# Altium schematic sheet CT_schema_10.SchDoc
size 274 x 160 mm
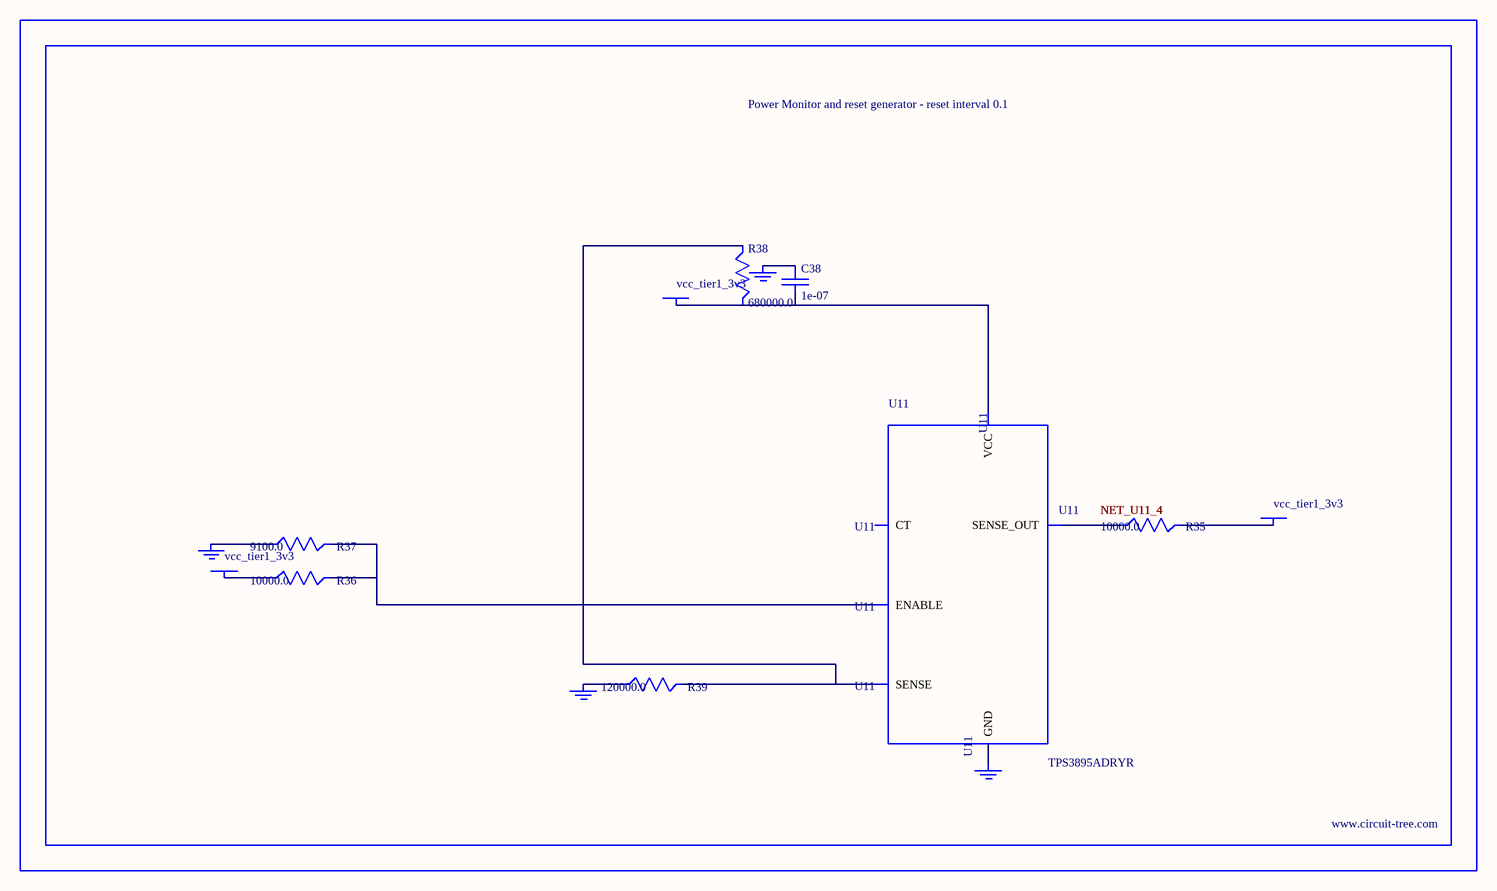
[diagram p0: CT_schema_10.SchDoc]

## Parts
BORDER9  (no value)
C38  1e-07  [C0402]
GND_INSTANCE_9_0  (no value)
GND_INSTANCE_9_1  (no value)
GND_INSTANCE_9_2  (no value)
GND_INSTANCE_9_3  (no value)
POWER_INSTANCE_9_0  vcc_tier1_3v3
POWER_INSTANCE_9_1  vcc_tier1_3v3
POWER_INSTANCE_9_2  vcc_tier1_3v3
R35  10000.0  [R0603]
R36  10000.0  [R0603]
R37  9100.0  [R0603]
R38  680000.0  [R0603]
R39  120000.0  [R0603]
U11  TPS3895ADRYR  [SON-6]

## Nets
NetC38_1: C38.1 GND_INSTANCE_9_2.0(GND)
NetC38_2: C38.2 POWER_INSTANCE_9_2.0(PWR) R38.2 U11.6(VCC)
NetGND_INSTANCE_9_0_0: GND_INSTANCE_9_0.0(GND) R37.1
NetGND_INSTANCE_9_1_0: GND_INSTANCE_9_1.0(GND) R39.1
NetGND_INSTANCE_9_3_0: GND_INSTANCE_9_3.0(GND) U11.2(GND)
NetPOWER_INSTANCE_9_0_0: POWER_INSTANCE_9_0.0(PWR) R36.1
NetPOWER_INSTANCE_9_1_0: POWER_INSTANCE_9_1.0(PWR) R35.2
NetR35_1: R35.1 U11.4(SENSE_OUT)
NetR36_2: R36.2 R37.2 U11.1(ENABLE)
NetR38_1: R38.1 R39.2 U11.3(SENSE)

Not connected (* = marked no-connect by the designer): U11 5(CT)

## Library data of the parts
BORDER9 = BORDER_PAGE9
C38 = C0402C104K3RACTU
GND_INSTANCE_9_0-GND_INSTANCE_9_3 = GND
POWER_INSTANCE_9_0-POWER_INSTANCE_9_2 = PWR
R35 R36 = RC0603JR-0710KL
R37 = RC0603JR-079K1L
R38 = RC0603JR-07680KL
R39 = RC0603JR-07120KL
